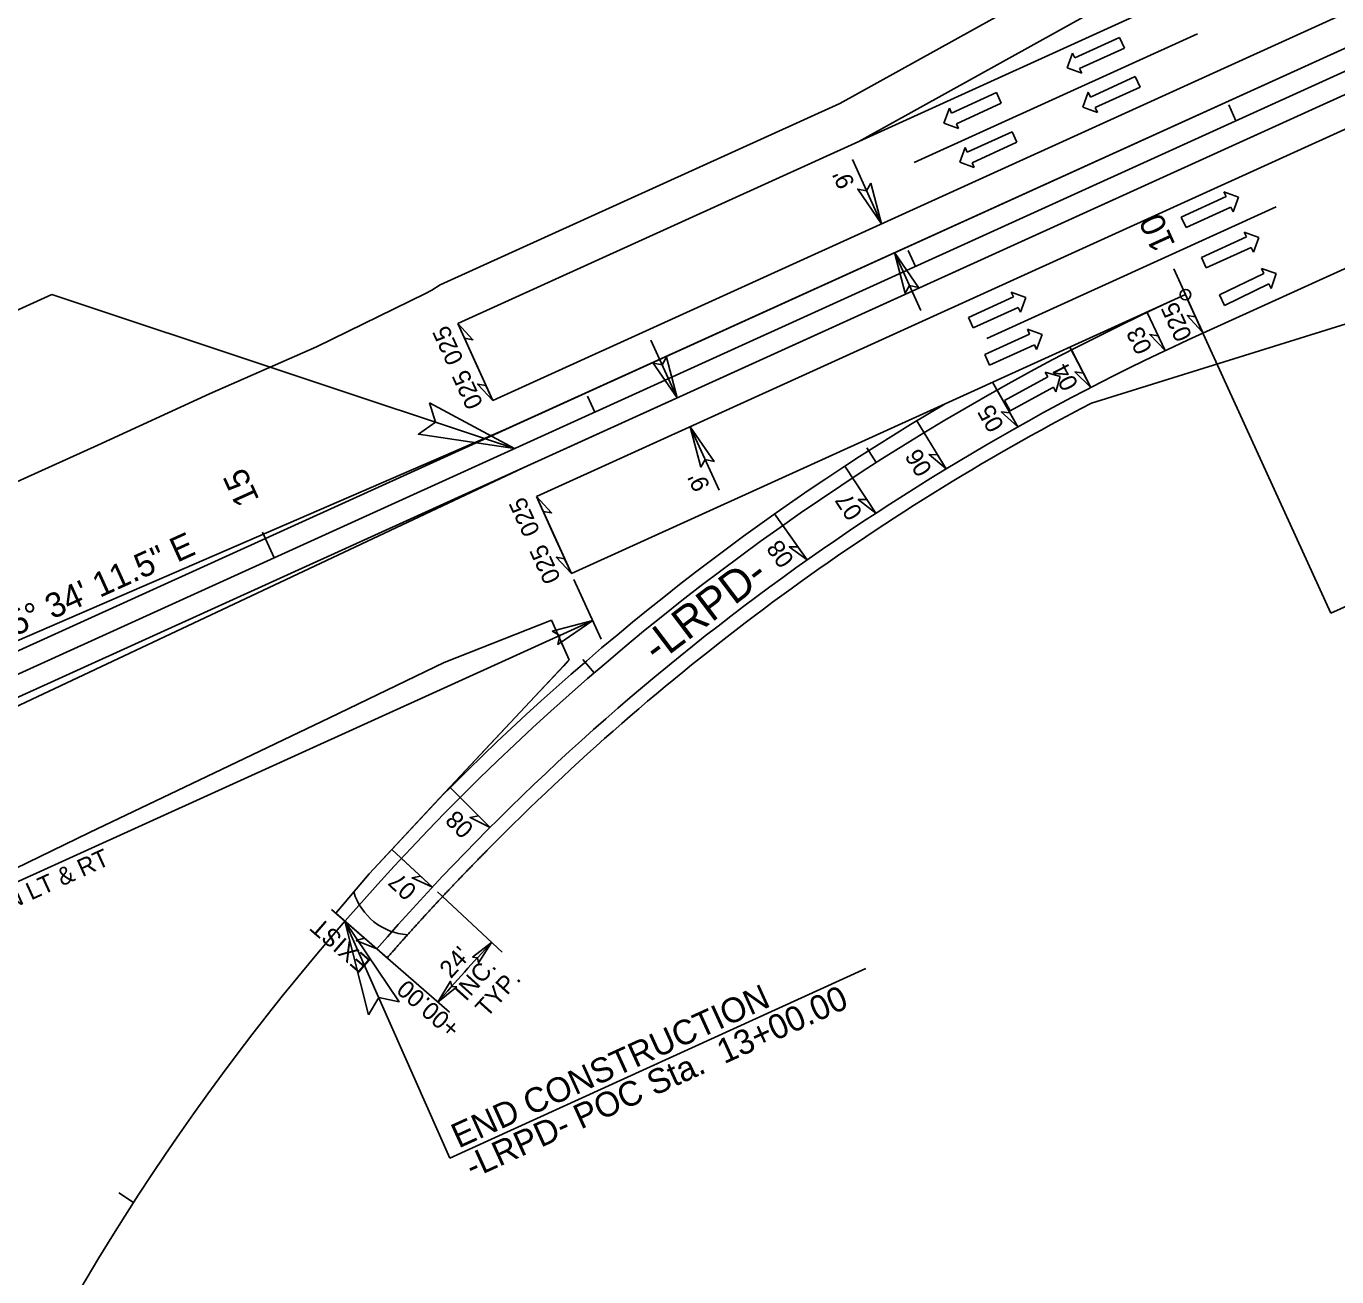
# Model space of a CAD drawing. Extents: x 2242984 to 2250974, y 661492 to 664681.
# Drawn here: x 2248067.7 to 2248439.9, y 662790.3 to 663145.5 of the extents above; entities that cross this region are included whole.
import ezdxf

# ---------------------------------------------------------------- set-up
doc = ezdxf.new("R2010")
doc.units = 0
for name, color, linetype in [('Prop Dimension', 7, 'Continuous'), ('Prop Dimension Text', 7, 'Continuous'), ('Prop EOT', 7, 'Continuous'), ('Prop Guardrail', 7, 'Continuous'), ('Prop Horizontal Alignment', 7, 'Continuous'), ('Prop Horizontal Alignment Curve and Spiral Data', 7, 'Continuous'), ('Prop Horizontal Alignment Direction Label', 7, 'Continuous'), ('Prop Horizontal Alignment Station Label', 7, 'Continuous'), ('Prop Horizontal Alignment Tick Label', 7, 'Continuous'), ('Prop Horizontal Alignment Tick Large', 7, 'Continuous'), ('Prop Horizontal Alignment Tick Small', 7, 'Continuous'), ('Prop Lane Arrow CELL', 7, 'Continuous'), ('Prop Lane Lines', 7, 'Continuous'), ('Prop Paved Shoulder', 7, 'Continuous'), ('Prop Shade Medium', 7, 'Continuous'), ('Prop Superelevation  Arrow CELL', 7, 'Continuous'), ('Prop Superelevation Label', 7, 'Continuous'), ('Prop Terminator CELL', 7, 'Continuous'), ('Scratch_Level_0', 7, 'Continuous'), ('Scratch_Level_2', 7, 'Continuous'), ('Typical Terminator CELL', 7, 'Continuous')]:
    doc.layers.add(name, color=color, linetype=linetype)

# ---------------------------------------------------------------- blocks, each defined once
blk = doc.blocks.new('TERMINATOR')
at = {"layer": 'Typical Terminator CELL'}
blk.add_lwpolyline([(-0.469, 0.081), (0, 0), (-0.471, -0.083), (-0.411, 0)], close=True, dxfattribs=at)

msp = doc.modelspace()

# ---------------------------------------------------------------- linework, layer by layer
at = {"layer": 'Prop Dimension'}
for p, q in [((2248302.35, 663107.58), (2248310.63, 663089.36)), ((2248321.81, 663064.74), (2248314.35, 663081.17)), ((2247823.34, 662954.6), (2248075.06, 663069.31)), ((2248206.41, 663025.54), (2248075.06, 663069.31)), ((2248245.12, 663056.35), (2248252.58, 663039.92)), ((2248264.5, 663013.68), (2248256.3, 663031.73)), ((2248223.29, 662988.37), (2248231.02, 662971.37)), ((2248228.6, 662976.68), (2247887.17, 662821.59)), ((2248202.88, 662882.5), (2248184.52, 662899.61)), ((2248187.94, 662865.46), (2248169.02, 662881.92))]:
    msp.add_line(p, q, dxfattribs=at)
msp.add_arc((2248686.42, 662431.92), 665, 137.02103, 138.98546, dxfattribs=at)
at = {"layer": 'Prop EOT'}
for p, q in [((2248200.21, 663039.2), (2249433.89, 663599.6)), ((2248212.61, 663011.89), (2249446.3, 663572.29)), ((2248401.88, 663058.32), (2249188.04, 663415.44)), ((2248304.14, 663112.77), (2248435.75, 663185.74)), ((2248190.28, 663061.05), (2248304.14, 663112.77)), ((2248200.21, 663039.2), (2248190.28, 663061.05)), ((2248222.54, 662990.03), (2248212.61, 663011.89))]:
    msp.add_line(p, q, dxfattribs=at)
msp.add_lwpolyline([(2248183.98, 662924.97), (2248187.11, 662928.33), (2248196.63, 662938.54), (2248202.2, 662944.48), (2248208.09, 662950.76), (2248212.13, 662955.07), (2248217.26, 662960.54), (2248220.37, 662963.86), (2248221.64, 662965.21), (2248221.9, 662965.48), (2248219.46, 662971.01), (2248216.92, 662976.74)], dxfattribs=at)
msp.add_arc((2248686.42, 662431.92), 688, 114.43013, 138.98546, dxfattribs=at)
at = {"layer": 'Prop Guardrail'}
for p, q in [((2248855.32, 663313.72), (2247994.71, 662922.79)), ((2248855.32, 663313.72), (2247994.71, 662922.79)), ((2247989.75, 662933.71), (2248810.53, 663306.55)), ((2247989.75, 662933.71), (2248810.53, 663306.55))]:
    msp.add_line(p, q, dxfattribs=at)
at = {"layer": 'Prop Horizontal Alignment'}
msp.add_line((2247500.8, 662705.02), (2249793.08, 663746.29), dxfattribs=at)
msp.add_arc((2248686.42, 662431.92), 700, 114.43013, 150.99406, dxfattribs=at)
at = {"layer": 'Prop Horizontal Alignment Station Label'}
for p, q in [((2248397.54, 663067.88), (2248401.72, 663058.69)), ((2248397.54, 663067.88), (2248438.16, 662978.73)), ((2248591, 663048.38), (2248438.16, 662978.73)), ((2248188.01, 662824.03), (2248158.24, 662891.29)), ((2248188.01, 662824.03), (2248306.16, 662877.87))]:
    msp.add_line(p, q, dxfattribs=at)
msp.add_circle((2248396.91, 663069.24), 1.5, dxfattribs=at)
at = {"layer": 'Prop Horizontal Alignment Tick Large'}
for p, q in [((2248393.61, 663076.53), (2248396.91, 663069.24)), ((2248138.12, 662994.52), (2248134.82, 663001.81))]:
    msp.add_line(p, q, dxfattribs=at)
at = {"layer": 'Prop Horizontal Alignment Tick Small'}
for p, q in [((2248411.26, 663118.6), (2248409.2, 663123.15)), ((2248320.22, 663077.24), (2248318.15, 663081.79)), ((2248229.17, 663035.88), (2248227.1, 663040.43)), ((2248306.43, 663025.75), (2248309.13, 663021.53)), ((2248225.76, 662965.6), (2248229.03, 662961.81)), ((2248154.47, 662894.58), (2248158.24, 662891.29)), ((2248094.02, 662814.13), (2248098.22, 662811.42))]:
    msp.add_line(p, q, dxfattribs=at)
at = {"layer": 'Prop Lane Arrow CELL'}
for p, q in [((2248365.47, 663136.46), (2248378.21, 663142.27)), ((2248378.21, 663142.27), (2248379.58, 663139.27)), ((2248363.31, 663133.61), (2248364.85, 663137.83)), ((2248364.85, 663137.83), (2248365.47, 663136.46)), ((2248379.58, 663139.27), (2248366.84, 663133.46)), ((2248367.46, 663132.1), (2248363.31, 663133.61)), ((2248366.84, 663133.46), (2248367.46, 663132.1)), ((2248369.93, 663125.36), (2248382.67, 663131.17)), ((2248382.67, 663131.17), (2248384.04, 663128.17)), ((2248330.51, 663120.79), (2248343.25, 663126.6)), ((2248343.25, 663126.6), (2248344.62, 663123.6)), ((2248367.77, 663122.51), (2248369.31, 663126.73)), ((2248369.31, 663126.73), (2248369.93, 663125.36)), ((2248384.04, 663128.17), (2248371.3, 663122.36)), ((2248328.35, 663117.94), (2248329.89, 663122.16)), ((2248329.89, 663122.16), (2248330.51, 663120.79)), ((2248344.62, 663123.6), (2248331.88, 663117.79)), ((2248371.92, 663121), (2248367.77, 663122.51)), ((2248371.3, 663122.36), (2248371.92, 663121)), ((2248332.51, 663116.43), (2248328.35, 663117.94)), ((2248331.88, 663117.79), (2248332.51, 663116.43)), ((2248334.98, 663109.69), (2248347.72, 663115.5)), ((2248347.72, 663115.5), (2248349.08, 663112.5)), ((2248332.81, 663106.84), (2248334.35, 663111.06)), ((2248334.35, 663111.06), (2248334.98, 663109.69)), ((2248349.08, 663112.5), (2248336.34, 663106.69)), ((2248336.97, 663105.33), (2248332.81, 663106.84)), ((2248336.34, 663106.69), (2248336.97, 663105.33)), ((2248395.72, 663091.27), (2248408.46, 663097.08)), ((2248408.46, 663097.08), (2248407.84, 663098.44)), ((2248407.84, 663098.44), (2248411.99, 663096.93)), ((2248411.99, 663096.93), (2248410.45, 663092.71)), ((2248397.09, 663088.27), (2248395.72, 663091.27)), ((2248409.83, 663094.08), (2248397.09, 663088.27)), ((2248410.45, 663092.71), (2248409.83, 663094.08)), ((2248401.48, 663079.83), (2248414.22, 663085.63)), ((2248414.22, 663085.63), (2248413.59, 663087)), ((2248413.59, 663087), (2248417.75, 663085.48)), ((2248417.75, 663085.48), (2248416.21, 663081.27)), ((2248415.58, 663082.63), (2248402.85, 663076.83)), ((2248416.21, 663081.27), (2248415.58, 663082.63)), ((2248402.85, 663076.83), (2248401.48, 663079.83)), ((2248419.14, 663075.28), (2248418.49, 663076.63)), ((2248418.49, 663076.63), (2248422.68, 663075.21)), ((2248406.55, 663069.15), (2248419.14, 663075.28)), ((2248422.68, 663075.21), (2248421.24, 663070.96)), ((2248348.05, 663068.6), (2248347.43, 663069.96)), ((2248347.43, 663069.96), (2248351.58, 663068.45)), ((2248408, 663066.19), (2248406.55, 663069.15)), ((2248420.59, 663072.31), (2248408, 663066.19)), ((2248421.24, 663070.96), (2248420.59, 663072.31)), ((2248335.31, 663062.79), (2248348.05, 663068.6)), ((2248349.42, 663065.59), (2248336.68, 663059.79)), ((2248350.04, 663064.23), (2248349.42, 663065.59)), ((2248351.58, 663068.45), (2248350.04, 663064.23)), ((2248336.68, 663059.79), (2248335.31, 663062.79)), ((2248339.93, 663052.22), (2248352.67, 663058.02)), ((2248352.67, 663058.02), (2248352.04, 663059.39)), ((2248352.04, 663059.39), (2248356.2, 663057.87)), ((2248356.2, 663057.87), (2248354.66, 663053.66)), ((2248354.03, 663055.02), (2248341.29, 663049.22)), ((2248354.66, 663053.66), (2248354.03, 663055.02)), ((2248341.29, 663049.22), (2248339.93, 663052.22)), ((2248357.82, 663045.89), (2248357.1, 663047.21)), ((2248357.1, 663047.21), (2248361.35, 663046)), ((2248345.54, 663039.16), (2248357.82, 663045.89)), ((2248359.41, 663043), (2248347.13, 663036.27)), ((2248360.13, 663041.68), (2248359.41, 663043)), ((2248361.35, 663046), (2248360.13, 663041.68)), ((2248347.13, 663036.27), (2248345.54, 663039.16))]:
    msp.add_line(p, q, dxfattribs=at)
at = {"layer": 'Prop Lane Lines'}
for p, q in [((2248304.14, 663112.77), (2248668.27, 663278.18)), ((2248319.85, 663106.73), (2248400.36, 663143.3)), ((2248340.5, 663056.8), (2248422.69, 663094.13)), ((2248328.68, 663038.25), (2248396.91, 663069.24)), ((2248222.54, 662990.03), (2248328.68, 663038.25))]:
    msp.add_line(p, q, dxfattribs=at)
msp.add_arc((2248686.42, 662431.92), 704, 120.54077, 135.40471, dxfattribs=at)
at = {"layer": 'Prop Paved Shoulder'}
for p, q in [((2248203.91, 663031), (2248894.79, 663344.83)), ((2248208.89, 663020.08), (2248895.78, 663332.1)), ((2248298.74, 663123.5), (2248378.08, 663167.49)), ((2248185.32, 663071.98), (2248298.74, 663123.5)), ((2248601.09, 663110.37), (2248370.21, 663038.44)), ((2248185.32, 663071.98), (2248182.96, 663070.48)), ((2247868.29, 662885.73), (2248203.91, 663031)), ((2247869.62, 662860.25), (2248208.86, 663020.07)), ((2248155.65, 662893.55), (2248165.12, 662904.72))]:
    msp.add_line(p, q, dxfattribs=at)
for points in [[(2247708.16, 662853), (2247737.81, 662866.51), (2247762.85, 662877.4), (2247800.12, 662895.08), (2247832.44, 662909.7), (2247861.63, 662923.16), (2247885.32, 662933.83), (2247909.61, 662945.06), (2247924.85, 662952.02), (2247966.34, 662970.9), (2247994.49, 662983.87), (2248025.59, 662998.19), (2248058.08, 663012.97), (2248088.08, 663026.44), (2248119.82, 663041.08), (2248150.21, 663054.44), (2248181.1, 663069.6), (2248182.96, 663070.48)], [(2247748.12, 662765.04), (2247749.91, 662765.84), (2247788.02, 662782.85), (2247819.89, 662797), (2247858.38, 662814.46), (2247890.52, 662828.54), (2247929.75, 662846.07), (2247965.79, 662862.18), (2248016.34, 662884.69), (2248053.87, 662901.09), (2248085.69, 662916.48), (2248123.17, 662934.34), (2248153.89, 662949.09), (2248186.42, 662964.72), (2248216.92, 662976.74)], [(2248216.92, 662976.74), (2248221.9, 662965.48), (2248194.06, 662935.8), (2248165.12, 662904.72)]]:
    msp.add_lwpolyline(points, dxfattribs=at)
msp.add_arc((2248686.42, 662431.92), 684, 117.53576, 134.8929, dxfattribs=at)
msp.add_spline([(2248203.67, 662916.48), (2248203.2, 662916.02), (2248202.73, 662915.55), (2248202.26, 662915.09), (2248201.79, 662914.62), (2248201.33, 662914.15), (2248200.86, 662913.69), (2248200.4, 662913.22), (2248199.93, 662912.75), (2248199.46, 662912.28), (2248199, 662911.81), (2248198.54, 662911.34), (2248198.07, 662910.87), (2248197.61, 662910.4), (2248197.15, 662909.93), (2248196.68, 662909.46), (2248196.22, 662908.99), (2248195.76, 662908.52), (2248195.3, 662908.04), (2248194.84, 662907.57), (2248194.38, 662907.1), (2248193.92, 662906.62), (2248193.46, 662906.15), (2248193, 662905.67), (2248192.54, 662905.2), (2248192.08, 662904.72), (2248191.63, 662904.25), (2248191.17, 662903.77), (2248190.71, 662903.29), (2248190.26, 662902.82), (2248189.8, 662902.34), (2248189.35, 662901.86), (2248188.89, 662901.38), (2248188.44, 662900.9), (2248187.98, 662900.42), (2248187.53, 662899.94), (2248187.08, 662899.46), (2248186.62, 662898.98), (2248186.17, 662898.5), (2248185.72, 662898.02), (2248185.27, 662897.54), (2248184.82, 662897.05), (2248184.37, 662896.57), (2248183.92, 662896.09), (2248183.47, 662895.6), (2248183.02, 662895.12), (2248182.57, 662894.63), (2248182.13, 662894.15), (2248181.68, 662893.66), (2248181.23, 662893.17), (2248180.79, 662892.69), (2248180.34, 662892.2), (2248179.9, 662891.71), (2248179.45, 662891.23), (2248179.01, 662890.74), (2248178.56, 662890.25), (2248178.12, 662889.76), (2248177.68, 662889.27), (2248177.23, 662888.78), (2248176.79, 662888.29), (2248176.35, 662887.8), (2248175.91, 662887.31), (2248175.47, 662886.81), (2248175.03, 662886.32), (2248174.59, 662885.83), (2248174.15, 662885.34), (2248173.71, 662884.84), (2248173.27, 662884.35), (2248172.83, 662883.85), (2248172.4, 662883.36), (2248171.96, 662882.86), (2248171.52, 662882.37), (2248171.09, 662881.87), (2248170.22, 662880.88)], degree=3, dxfattribs=at)
at = {"layer": 'Prop Shade Medium'}
for p, q in [((2248155.65, 662893.55), (2248170.22, 662880.88)), ((2248170.22, 662880.88), (2248176.02, 662887.43))]:
    msp.add_line(p, q, dxfattribs=at)
msp.add_lwpolyline([(2248160.77, 662899.59), (2248158.44, 662896.84), (2248155.65, 662893.55)], dxfattribs=at)
msp.add_arc((2248177.17, 662904.52), 17.13, 196.7159, 266.1309, dxfattribs=at)
at = {"layer": 'Prop Superelevation  Arrow CELL'}
for p, q in [((2248401.71, 663058.69), (2248396.75, 663069.61)), ((2248401.71, 663058.69), (2248396.91, 663069.24)), ((2248391.18, 663053.35), (2248386.03, 663064.19)), ((2248391.18, 663053.35), (2248386.03, 663064.19)), ((2248190.28, 663061.05), (2248195.24, 663050.12)), ((2248370.05, 663042.86), (2248364.11, 663054.34)), ((2248370.05, 663042.86), (2248364.54, 663053.52)), ((2248200.21, 663039.2), (2248195.24, 663050.12)), ((2248349.3, 663031.66), (2248342.15, 663044.37)), ((2248349.3, 663031.66), (2248343.42, 663042.12)), ((2248328.94, 663019.75), (2248320.62, 663033.42)), ((2248328.94, 663019.75), (2248322.7, 663030)), ((2248309, 663007.15), (2248300.22, 663020.53)), ((2248309, 663007.15), (2248302.41, 663017.18)), ((2248212.61, 663011.89), (2248217.58, 663000.96)), ((2248289.5, 662993.88), (2248280.27, 663006.94)), ((2248289.5, 662993.88), (2248282.58, 663003.68)), ((2248222.54, 662990.03), (2248217.58, 663000.96)), ((2248199.45, 662917.93), (2248188.03, 662929.33)), ((2248199.45, 662917.93), (2248190.96, 662926.4)), ((2248183.08, 662900.95), (2248174.3, 662909.13)), ((2248167.3, 662883.42), (2248158.24, 662891.29))]:
    msp.add_line(p, q, dxfattribs=at)
for points in [[(2248401.71, 663058.69), (2248397.41, 663063.32), (2248399.8, 663062.9)], [(2248190.28, 663061.05), (2248194.58, 663056.41), (2248192.19, 663056.84)], [(2248391.18, 663053.35), (2248386.8, 663057.91), (2248389.2, 663057.53)], [(2248370.05, 663042.86), (2248365.52, 663047.27), (2248367.93, 663046.97)], [(2248200.21, 663039.2), (2248195.9, 663043.83), (2248198.29, 663043.41)], [(2248349.3, 663031.66), (2248344.61, 663035.91), (2248347.03, 663035.69)], [(2248328.94, 663019.75), (2248324.11, 663023.84), (2248326.53, 663023.7)], [(2248212.61, 663011.89), (2248216.92, 663007.25), (2248214.53, 663007.67)], [(2248309, 663007.15), (2248304.03, 663011.07), (2248306.46, 663011.02)], [(2248222.54, 662990.03), (2248218.24, 662994.67), (2248220.63, 662994.24)], [(2248289.5, 662993.88), (2248284.4, 662997.62), (2248286.83, 662997.65)], [(2248199.45, 662917.93), (2248193.79, 662920.75), (2248196.18, 662921.19)], [(2248183.08, 662900.95), (2248177.33, 662903.58), (2248179.7, 662904.1)], [(2248167.3, 662883.42), (2248161.46, 662885.85), (2248163.81, 662886.45)]]:
    msp.add_lwpolyline(points, close=True, dxfattribs=at)
at = {"layer": 'Prop Superelevation Label'}
msp.add_line((2248183.08, 662900.95), (2248171.58, 662911.66), dxfattribs=at)
at = {"layer": 'Prop Terminator CELL'}
for points in [[(2248182.26, 663038.49), (2248206.41, 663025.54), (2248179.13, 663029.57), (2248183.92, 663033.03)], [(2248164.92, 662864.72), (2248158.24, 662891.29), (2248173.62, 662868.41), (2248167.83, 662869.62)], [(2248194.47, 662881.1), (2248199.91, 662885.27), (2248196.18, 662879.47), (2248195.89, 662880.92)], [(2248189.98, 662872.63), (2248184.65, 662868.33), (2248188.23, 662874.22), (2248188.56, 662872.78)]]:
    msp.add_lwpolyline(points, close=True, dxfattribs=at)
at = {"layer": 'Scratch_Level_0'}
msp.add_line((2248155.63, 662893.57), (2248165.1, 662904.73), dxfattribs=at)
for points in [[(2248221.88, 662965.5), (2248194.05, 662935.82), (2248185.1, 662926.21)], [(2248185.1, 662926.21), (2248165.1, 662904.73)]]:
    msp.add_lwpolyline(points, dxfattribs=at)
at = {"layer": 'Scratch_Level_2'}
for p, q in [((2248298.74, 663123.5), (2248378.08, 663167.49)), ((2248185.32, 663071.98), (2248298.74, 663123.5)), ((2248185.32, 663071.98), (2248182.96, 663070.48))]:
    msp.add_line(p, q, dxfattribs=at)
for points in [[(2247708.16, 662853), (2247737.81, 662866.51), (2247762.85, 662877.4), (2247800.12, 662895.08), (2247832.44, 662909.7), (2247861.63, 662923.16), (2247885.32, 662933.83), (2247909.61, 662945.06), (2247924.85, 662952.02), (2247966.34, 662970.9), (2247994.49, 662983.87), (2248025.59, 662998.19), (2248058.08, 663012.97), (2248088.08, 663026.44), (2248119.82, 663041.08), (2248150.21, 663054.44), (2248181.1, 663069.6), (2248182.96, 663070.48)], [(2247748.12, 662765.04), (2247749.91, 662765.84), (2247788.02, 662782.85), (2247819.89, 662797), (2247858.38, 662814.46), (2247890.52, 662828.54), (2247929.75, 662846.07), (2247965.79, 662862.18), (2248016.34, 662884.69), (2248053.87, 662901.09), (2248085.69, 662916.48), (2248123.17, 662934.34), (2248153.89, 662949.09), (2248186.42, 662964.72), (2248216.92, 662976.74)]]:
    msp.add_lwpolyline(points, dxfattribs=at)

# ---------------------------------------------------------------- block references
at = {"layer": 'Prop Dimension'}
for p, xscale, yscale, rotation in [((2248310.63, 663089.36), 25, 25, -65.56987410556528), ((2248314.35, 663081.17), 25, 25.00000000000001, 114.43012589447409), ((2248252.58, 663039.92), 25, 25, -65.56987410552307), ((2248256.3, 663031.73), 25, 25, 114.43012589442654), ((2248228.6, 662976.68), 24.999999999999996, 25, 24.43012589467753)]:
    msp.add_blockref('TERMINATOR', p, dxfattribs=dict(at, xscale=xscale, yscale=yscale, rotation=rotation))

# ---------------------------------------------------------------- texts
for s, rotation, p in [("9'", 114.4301, (2248303.12, 663100.77)), ("9'", 114.4301, (2248262.03, 663014.8)), ("24'", 48.0032, (2248188.34, 662874.79)), ('INC.', 48.0032, (2248192.61, 662868.32)), ('TYP.', 48.0032, (2248198.56, 662863.72)), ('+00.00', 138.9855, (2248191.37, 662861.47))]:
    msp.add_text(s, height=5, rotation=rotation, dxfattribs=at).set_placement(p)
at = {"layer": 'Prop Dimension Text'}
msp.add_text("375' MEDIAN TRANSITION LT & RT", height=5, rotation=24.4979, dxfattribs=at).set_placement((2247992.24, 662862.13))
at = {"layer": 'Prop Horizontal Alignment Curve and Spiral Data'}
msp.add_text('-LRPD-', height=9, rotation=37.1625, dxfattribs=at).set_placement((2248246.94, 662964.32))
at = {"layer": 'Prop Horizontal Alignment Direction Label'}
msp.add_text('N 65%%d 34\' 11.5" E', height=7, rotation=24.4301, dxfattribs=at).set_placement((2248051.36, 662966.16))
at = {"layer": 'Prop Horizontal Alignment Station Label'}
for s, p in [('END CONSTRUCTION', (2248190.53, 662826.71)), ('-LRPD- POC Sta.  13+00.00', (2248194.46, 662818.08))]:
    msp.add_text(s, height=7, rotation=24.4979, dxfattribs=at).set_placement(p)
at = {"layer": 'Prop Horizontal Alignment Tick Label'}
for s, p in [('10', (2248394.17, 663083.47)), ('15', (2248134.04, 663011.04))]:
    msp.add_text(s, height=7, rotation=114.4301, dxfattribs=at).set_placement(p)
at = {"layer": 'Prop Superelevation Label'}
for s, rotation, p in [('025', 114.4301, (2248398.93, 663057.43)), ('025', 114.4979, (2248192.05, 663050.73)), ('03', 115.4123, (2248387.62, 663053.9)), ('025', 114.4979, (2248197.6, 663038.19)), ('04', 117.3768, (2248366.64, 663043.66)), ('05', 119.3412, (2248345.59, 663032.05)), ('06', 121.3056, (2248325.17, 663019.61)), ('025', 114.4979, (2248213.77, 663002)), ('07', 123.27, (2248305.44, 663007.3)), ('025', 114.4979, (2248219.63, 662988.6)), ('08', 125.2345, (2248286.02, 662993.99)), ('08', 135.0566, (2248195.15, 662917.91)), ('07', 137.021, (2248179, 662900.46)), ('EXIST', 138.9855, (2248165.91, 662879.95))]:
    msp.add_text(s, height=5, rotation=rotation, dxfattribs=at).set_placement(p)

doc.saveas('drawing.dxf')
